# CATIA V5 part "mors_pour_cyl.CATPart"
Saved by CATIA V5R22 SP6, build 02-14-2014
Part number: mors_pour_cyl
Bounding box of the stored display mesh (mm): x -45 to 45, y -20 to 20, z -1.8 to 16
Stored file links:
  C:\Users\kremer\Desktop\demo_5x\mors_pour_cyl.CATPart
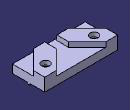
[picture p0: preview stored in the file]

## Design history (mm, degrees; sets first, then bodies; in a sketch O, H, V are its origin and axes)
Body1 (main body)
  Sketch1 on xy-plane, origin (0, 0, 0), H (1, 0, 0), V (0, 1, 0)
    line L1 (45, 20) -> (45, -20)
    line L2 (45, -20) -> (-45, -20)
    line L3 (-45, -20) -> (-45, 20)
    line L4 (-45, 20) -> (45, 20)
    distance L4 L2 = 40
    distance L1 L3 = 90
    vertical: L1 V, L3 V
    horizontal: L2 H, L4 H
    equidistance: L1 L3 O, L2 L4 O
  Pad1: profile Sketch1, direction (0, 0, 1), length 10
  Sketch2 on end face of Pad1, origin (0, 0, 10), H (1, 0, 0), V (0, 1, 0)
    line L1 (-30.8579, 20) -> (-7.5, -3.3579)
    point P1 (-7.5, -3.3579)
    reference intersected line E1 (-45, 20) -> (45, 20) from face of Pad1 from Sketch1.L4
    line L2 (-45, 20) -> (-30.8579, 20)
    reference intersected line E3 (-45, 20) -> (45, 20) from face of Pad1 from Sketch1.L4
    line L3 (-45, 20) -> (-45, 5.8579)
    point P4 (-45, 5.8579)
    reference intersected line E4 (-45, -20) -> (-45, 20) from face of Pad1 from Sketch1.L3
    point P5 (-30.8579, 20)
    point P6 (-45, 20)
    line L4 (-45, 5.8579) -> (-21.6421, -17.5)
    point P7 (-21.6421, -17.5)
    line L5 (-21.6421, -17.5) -> (-7.5, -17.5)
    line L6 (-7.5, -3.3579) -> (-7.5, -17.5)
    point P8 (-7.5, -17.5)
    axis line L7 (-45, 20) -> (-7.5, -17.5)
    reference intersected line E5 through (0, 0) direction (0, 1) from yz-plane
    point P11 (45, 5.8579)
    point P12 (45, 20)
    line L8 (45, 20) -> (45, 5.8579)
    point P13 (30.8579, 20)
    line L9 (45, 20) -> (30.8579, 20)
    point P14 (7.5, -3.3579)
    line L10 (30.8579, 20) -> (7.5, -3.3579)
    point P15 (21.6421, -17.5)
    line L11 (45, 5.8579) -> (21.6421, -17.5)
    point P16 (7.5, -17.5)
    line L12 (21.6421, -17.5) -> (7.5, -17.5)
    line L13 (7.5, -3.3579) -> (7.5, -17.5)
    angle L1 E1 = 135
    distance L4 L1 = 20
    distance L6 L13 = 15
    coincidence: L2 E3, L3 E4
    equidistance: L4 L1 P6
    parallelism: L5 L2, L6 L3, L7 L1
    symmetry: P4 P11 E5, P6 P12 E5, L3 L8 E5, P5 P13 E5, L2 L9 E5, P1 P14 E5, L1 L10 E5, P7 P15 E5, L4 L11 E5, P8 P16 E5, L5 L12 E5, L6 L13 E5
  Pad2: profile Sketch2, direction (0, 0, 1), length 6
  Sketch3 on face of Pad2, origin (45, 0, 0), H (0, 1, 0), V (0, 0, 1)
    line L1 (-1.5, 0) -> (1.5, 0)
    line L2 (1.5, 0) -> (1.5, -1.8)
    line L3 (1.5, -1.8) -> (-1.5, -1.8)
    line L4 (-1.5, -1.8) -> (-1.5, 0)
    reference intersected line E1 (20, 0) -> (-20, 0) from start face of Pad1
    reference intersected line E2 through (0, 0) direction (0, 1) from zx-plane
    distance L3 L1 = 1.8
    distance L2 L4 = 3
    coincidence: L1 E1
    symmetry: L4 L2 E2
  Pad3: profile Sketch3, direction (1, 0, 0), up to face of Pad2
  Sketch4 on end face of Pad2, origin (31.4206, 6.7621, 16), H (1, 0, 0), V (0, 1, 0)
    point P1 (-1.4206, -0.7621)
    reference intersected line E1 through (0, -5.2621) direction (1, 0) from face of Pad3 from Sketch3.L2
    reference intersected line E2 through (-31.4206, 0) direction (0, 1) from yz-plane
    distance P1 E1 = 4.5
    distance E2 P1 = 30
  Hole1: placed by Sketch4, at (30, 6, 16) direction (0, 0, -1), diameter 6.2, through (limit type 3), counterbore diameter 10, counterbore depth 5
  Mirror1: of Hole1, about yz-plane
